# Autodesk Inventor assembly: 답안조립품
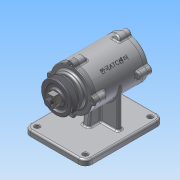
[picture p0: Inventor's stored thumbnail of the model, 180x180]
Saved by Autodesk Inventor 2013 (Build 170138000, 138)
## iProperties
Created: 2015-12
Part Number: 답안조립품
Document SubType Name: Assembly
Designer: Administrator
Author: Administrator
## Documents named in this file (11)
- C:\Users\Administrator\Desktop\451208V1023\답안조립품.iam
- C:\Users\Administrator\Desktop\451208V1023\본체.ipt
- C:\Users\Administrator\Desktop\451208V1023\커버.ipt
- C:\Users\Administrator\Desktop\451208V1023\커버2.ipt
- C:\Users\Administrator\Desktop\451208V1023\볼트 M4 x 12.ipt
- C:\Users\Administrator\Desktop\451208V1023\오일실.ipt
- C:\Users\Administrator\Desktop\451208V1023\베어링 6204.ipt
- C:\Users\Administrator\Desktop\451208V1023\축.ipt
- C:\Users\Administrator\Desktop\451208V1023\키(4 x 4 x 12).ipt
- C:\Users\Administrator\Desktop\451208V1023\V-벨트풀리.ipt
- C:\Users\Administrator\Desktop\451208V1023\너트 M12x1.25.ipt
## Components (6 placed, 5 different names)
1. KS B 2804 D D - 20 32 8:1
2. KS B 2023 6204 - 20 x 47 x 14:1
3. KS B 2023 6204 - 20 x 47 x 14:2
4. KS B 1311 (I) 4 x 4 x 12:1 — 각도:1, 각도:2, 각도:3
5. V-벨트풀리:1 — 각도:2
6. KS B 1012 클래스 1 일반 - 미터 M12x1.25:1
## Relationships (3: Angle 3)
- 각도:1 [Angle]: KS B 1311 (I) 4 x 4 x 12:1
- 각도:2 [Angle]: KS B 1311 (I) 4 x 4 x 12:1 ↔ V-벨트풀리:1
- 각도:3 [Angle]: KS B 1311 (I) 4 x 4 x 12:1
